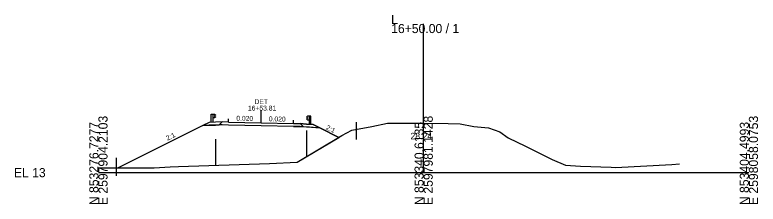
# Model space of a CAD drawing. Extents: x -26 to 1203, y -10 to 9526.
# Drawn here: x -25.7 to 202.8, y 6490.3 to 6548.5 of the extents above; entities that cross this region are included whole.
import ezdxf

# ---------------------------------------------------------------- set-up
doc = ezdxf.new("R2010")
doc.units = 0
for name, color, linetype in [('Exist Cross Section Cell', 7, 'Continuous'), ('Exist XS Center Line Elevation Label', 7, 'Continuous'), ('Exist XS Ground Line', 7, 'Continuous'), ('Prop XS Alignment Label', 7, 'Continuous'), ('Prop XS Earthwork Shape', 7, 'Continuous'), ('Prop XS EOT Tick Mark', 7, 'Continuous'), ('Prop XS Exc Vertical Line 1', 7, 'Continuous'), ('Prop XS Exc Vertical Line 2', 7, 'Continuous'), ('Prop XS Finish Grade', 7, 'Continuous'), ('Prop XS Finish Grade Earthwork', 7, 'Continuous'), ('Prop XS Finish Grade Paved Shoulder', 7, 'Continuous'), ('Prop XS Finish Grade Pavement', 7, 'Continuous'), ('Prop XS Guardrail', 7, 'Continuous'), ('Prop XS Pvmt Edge Slope', 7, 'Continuous'), ('Prop XS SE Text', 7, 'Continuous'), ('Prop XS Side Slope Text', 7, 'Continuous'), ('Prop XS Station Labels', 7, 'Continuous'), ('Prop XS Subgrade Earthwork', 7, 'Continuous'), ('Scratch_Level_1', 7, 'Continuous'), ('Scratch_Level_2', 7, 'Continuous')]:
    doc.layers.add(name, color=color, linetype=linetype)

msp = doc.modelspace()

# ---------------------------------------------------------------- linework, layer by layer
at = {"layer": 'Exist Cross Section Cell'}
for p, q in [((100, 6500), (100, 6545.73)), ((0, 6500), (100, 6500)), ((100, 6500), (200, 6500))]:
    msp.add_line(p, q, dxfattribs=at)
at = {"layer": 'Exist XS Ground Line'}
for p, q in [((77.91, 6513.11), (84.03, 6514.17)), ((84.03, 6514.17), (88.88, 6515.17)), ((88.88, 6515.17), (92.7, 6515.2)), ((92.7, 6515.2), (100.19, 6515.24)), ((100.19, 6515.24), (107.55, 6515.1)), ((107.55, 6515.1), (111.23, 6515.04)), ((111.23, 6515.04), (115.4, 6514.19)), ((115.4, 6514.19), (119.9, 6513.73)), ((119.9, 6513.73), (123.44, 6512.55)), ((61.15, 6503.24), (74.88, 6511.38)), ((74.88, 6511.38), (77.91, 6513.11)), ((123.44, 6512.55), (126.03, 6510.75)), ((126.03, 6510.75), (131.29, 6508.13)), ((131.29, 6508.13), (139.5, 6504)), ((17.09, 6501.43), (22.03, 6501.77)), ((22.03, 6501.77), (24.67, 6501.89)), ((24.67, 6501.89), (52.63, 6502.86)), ((52.63, 6502.86), (61.15, 6503.24)), ((139.5, 6504), (143.61, 6502.31)), ((143.61, 6502.31), (148.24, 6502.03)), ((148.24, 6502.03), (157.62, 6501.65)), ((158.94, 6501.57), (176.28, 6502.54)), ((176.28, 6502.54), (178.66, 6502.66)), ((0, 6501.46), (17.09, 6501.43)), ((157.62, 6501.65), (158.94, 6501.57))]:
    msp.add_line(p, q, dxfattribs=at)
at = {"layer": 'Prop XS Earthwork Shape'}
msp.add_lwpolyline([(60, 6514.23), (50, 6514.43), (40, 6514.63), (38, 6514.67), (37.1, 6514.69), (36, 6514.64), (34, 6514.56), (32.13, 6514.49), (6.05, 6501.45), (17.09, 6501.43), (22.03, 6501.77), (24.67, 6501.89), (52.63, 6502.86), (61.15, 6503.24), (73.94, 6510.82), (68.05, 6513.76), (66, 6513.92), (64.92, 6514.01), (63.98, 6514.03), (62, 6514.19)], close=True, dxfattribs=at)
at = {"layer": 'Prop XS EOT Tick Mark'}
for p, q in [((40, 6515.54), (40, 6516.54)), ((60, 6515.14), (60, 6516.14))]:
    msp.add_line(p, q, dxfattribs=at)
at = {"layer": 'Prop XS Exc Vertical Line 1'}
msp.add_line((5.46, 6504.55), (5.46, 6498.97), dxfattribs=at)
at = {"layer": 'Prop XS Exc Vertical Line 2'}
msp.add_line((79.27, 6515.49), (79.27, 6510.19), dxfattribs=at)
at = {"layer": 'Prop XS Finish Grade'}
for p, q in [((36, 6515.5), (34, 6515.42)), ((38, 6515.58), (36, 6515.5)), ((34, 6515.42), (32.13, 6514.49)), ((62, 6515.1), (64, 6514.94)), ((63.98, 6514.95), (64, 6514.94)), ((64, 6514.94), (66, 6514.78)), ((66, 6514.78), (68.05, 6513.76))]:
    msp.add_line(p, q, dxfattribs=at)
at = {"layer": 'Prop XS Finish Grade Earthwork'}
for p, q in [((32.13, 6514.49), (6.05, 6501.45)), ((68.05, 6513.76), (73.94, 6510.82))]:
    msp.add_line(p, q, dxfattribs=at)
at = {"layer": 'Prop XS Finish Grade Paved Shoulder'}
for p, q in [((40, 6515.54), (38, 6515.58)), ((60, 6515.14), (62, 6515.1))]:
    msp.add_line(p, q, dxfattribs=at)
at = {"layer": 'Prop XS Finish Grade Pavement'}
for p, q in [((40, 6515.54), (50, 6515.34)), ((50, 6515.34), (60, 6515.14))]:
    msp.add_line(p, q, dxfattribs=at)
at = {"layer": 'Prop XS Guardrail'}
for p, q in [((34.68, 6517.95), (35.18, 6517.95)), ((34.68, 6515.45), (34.68, 6517.95)), ((35.18, 6517.95), (35.68, 6517.95)), ((35.18, 6517.95), (35.18, 6515.45)), ((35.68, 6517.95), (35.97, 6517.75)), ((35.97, 6517.75), (36, 6517.69)), ((35.68, 6516.82), (35.18, 6516.82)), ((35.97, 6517.63), (35.68, 6517.43)), ((35.68, 6517.43), (35.68, 6517.34)), ((35.68, 6517.34), (35.97, 6517.14)), ((35.97, 6517.02), (35.68, 6516.82)), ((36, 6517.69), (35.97, 6517.63)), ((35.97, 6517.14), (36, 6517.08)), ((36, 6517.08), (35.97, 6517.02)), ((64.03, 6517.14), (64, 6517.08)), ((64, 6517.08), (64.03, 6517.02)), ((64.03, 6516.53), (64, 6516.47)), ((64, 6516.47), (64.03, 6516.41)), ((64.32, 6517.34), (64.03, 6517.14)), ((64.03, 6517.02), (64.32, 6516.82)), ((64.32, 6516.73), (64.03, 6516.53)), ((64.03, 6516.41), (64.32, 6516.21)), ((64.82, 6517.34), (64.32, 6517.34)), ((64.32, 6516.82), (64.32, 6516.73)), ((64.32, 6516.21), (64.82, 6516.21)), ((65.32, 6517.34), (64.82, 6517.34)), ((64.82, 6517.34), (64.82, 6514.84)), ((65.32, 6514.84), (65.32, 6517.34))]:
    msp.add_line(p, q, dxfattribs=at)
at = {"layer": 'Prop XS Pvmt Edge Slope'}
for p, q in [((38, 6515.58), (37.1, 6514.69)), ((62, 6515.1), (62.94, 6514.17))]:
    msp.add_line(p, q, dxfattribs=at)
at = {"layer": 'Prop XS Side Slope Text'}
msp.add_line((50, 6515.34), (50, 6519), dxfattribs=at)
at = {"layer": 'Prop XS Subgrade Earthwork'}
for p, q in [((34, 6514.56), (32.13, 6514.49)), ((36, 6514.64), (34, 6514.56)), ((37.1, 6514.69), (36, 6514.64)), ((38, 6514.67), (37.1, 6514.69)), ((40, 6514.63), (38, 6514.67)), ((50, 6514.43), (40, 6514.63)), ((60, 6514.23), (50, 6514.43)), ((60, 6514.23), (62.94, 6514.17)), ((62.94, 6514.17), (68.05, 6513.76))]:
    msp.add_line(p, q, dxfattribs=at)
at = {"layer": 'Scratch_Level_1'}
for points in [[(34, 6515.42), (32.13, 6514.49), (34, 6514.56), (36, 6514.64), (37.1, 6514.69), (38, 6515.58), (36, 6515.5)], [(62.94, 6514.17), (68.05, 6513.76), (66, 6514.78), (64, 6514.94), (63.98, 6514.95), (62, 6515.1)]]:
    msp.add_lwpolyline(points, close=True, dxfattribs=at)
at = {"layer": 'Scratch_Level_2'}
for p, q in [((64.02, 6512.94), (64.02, 6504.94)), ((35.97, 6510.28), (35.97, 6502.28))]:
    msp.add_line(p, q, dxfattribs=at)

# ---------------------------------------------------------------- texts
at = {"layer": 'Exist Cross Section Cell'}
for s, p in [('L', (90, 6545.73)), ('16+50.00 / 1', (90, 6542.93)), ('EL 13', (-26, 6498.6))]:
    msp.add_text(s, height=2.8, dxfattribs=at).set_placement(p)
for s, p in [('E 2597904.2103', (2.8, 6490)), ('E 2597981.1428', (102.8, 6490)), ('E 2598058.0753', (202.8, 6490)), ('N 853276.7277', (0, 6490)), ('N 853340.6135', (100, 6490)), ('N 853404.4993', (200, 6490))]:
    msp.add_text(s, height=2.8, rotation=90, dxfattribs=at).set_placement(p)
at = {"layer": 'Exist XS Center Line Elevation Label'}
msp.add_text('28.24', height=2, dxfattribs=at).set_placement((95.93, 6510.24))
at = {"layer": 'Prop XS Alignment Label'}
msp.add_text('DET', height=1.5, dxfattribs=at).set_placement((47.97, 6521.09))
at = {"layer": 'Prop XS SE Text'}
for p in [(42.38, 6516), (52.38, 6515.8)]:
    msp.add_text('0.020', height=1.5, rotation=358.8542, dxfattribs=at).set_placement(p)
at = {"layer": 'Prop XS Side Slope Text'}
for rotation, p in [(333.4349, (69.8, 6513.38)), (26.5651, (21.24, 6509.82))]:
    msp.add_text('2:1', height=1.5, rotation=rotation, dxfattribs=at).set_placement(p)
at = {"layer": 'Prop XS Station Labels'}
msp.add_text('16+53.81', height=1.5, dxfattribs=at).set_placement((45.98, 6519.09))

doc.saveas('drawing.dxf')
